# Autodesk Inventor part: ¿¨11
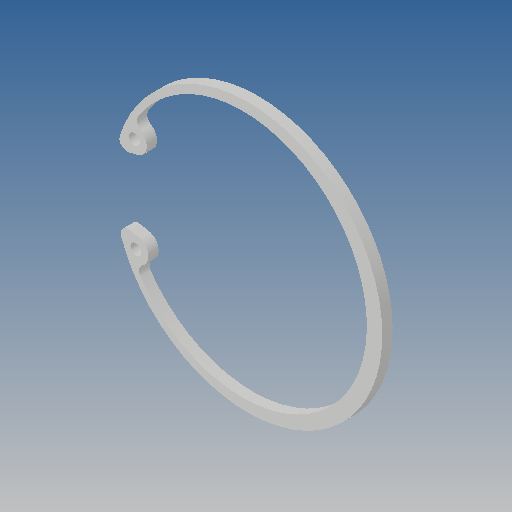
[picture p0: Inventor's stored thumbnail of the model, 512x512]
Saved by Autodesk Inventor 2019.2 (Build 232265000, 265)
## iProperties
Created: 2013-07
Part Number: ¿¨11
Material: Ogólny
Document SubType Name: Modeling
Designer: CADENGINEERING4
Density: 1 g/cm^3
Appearance: Domyślna
Author: CADENGINEERING4
Revision Number: ÈÎºÎ
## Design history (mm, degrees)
feature "11-1-solid1"
node "Bryła1"
